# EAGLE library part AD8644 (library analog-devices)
Single and Quad 18 V Operational Amplifiers Source: http://www.analog.com/static/imported-files/data_sheets/AD8614_8644.pdf
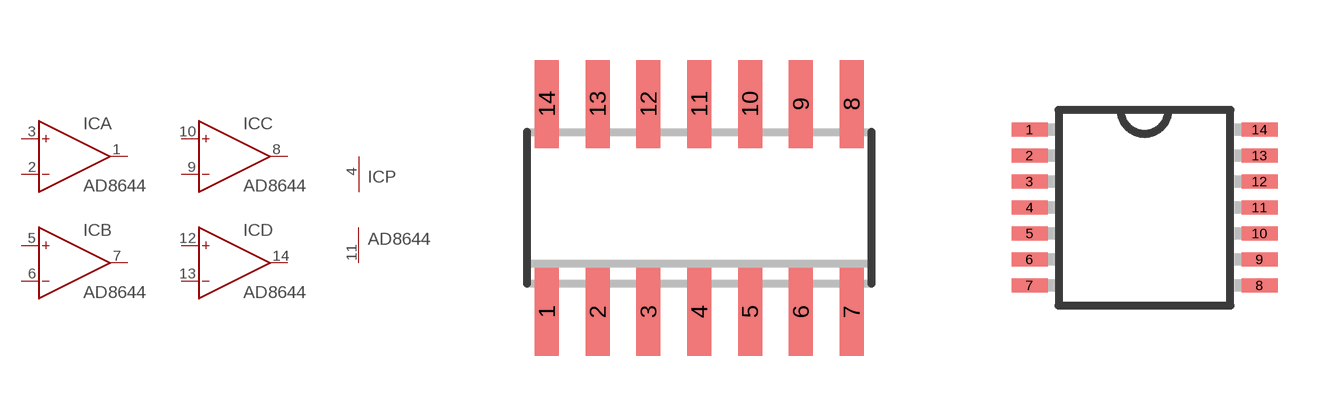
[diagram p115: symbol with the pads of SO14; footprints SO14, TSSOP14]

Designator prefix IC; gates A=OP B=OP C=OP D=OP P=PWR+-

## AD8644R (MF: ALTERA CORPORATION; MPN: AD8644ARZ; OC_FARNELL: 1438873; OC_NEWARK: 59K7037)  [SO14]
1  A:OUT  out
2  A:IN-  in
3  A:IN+  in
4  P:V+  pwr
5  B:IN+  in
6  B:IN-  in
7  B:OUT  out
8  C:OUT  out
9  C:IN-  in
10  C:IN+  in
11  P:V-  pwr
12  D:IN+  in
13  D:IN-  in
14  D:OUT  out

## AD8644RU (MF: ALTERA CORPORATION; MPN: AD8644ARUZ; OC_FARNELL: 1438873; OC_NEWARK: 59K7036)  [TSSOP14]
Pads as for SO14

## Footprint SO14 (pad centres in mm)
14-Lead Narrow-Body SOIC (SO-14) Source: http://www.analog.com/static/imported-files/data_sheets/SSM2166.pdf
smd 0.6 x 2.2: 1 -3.81,-2.6; 2 -2.54,-2.6; 3 -1.27,-2.6; 4 0,-2.6; 5 1.27,-2.6; 6 2.54,-2.6; 7 3.81,-2.6; 8 3.81,2.6; 9 2.54,2.6; 10 1.27,2.6; 11 0,2.6; 12 -1.27,2.6; 13 -2.54,2.6; 14 -3.81,2.6

## Footprint TSSOP14 (pad centres in mm)
14-Lead Thin Shrink Small Outline Package [TSSOP] Source: Analog Devices .. 780914713ADD8704_0.pdf
smd 0.9 x 0.35: 1 -2.875,1.95; 2 -2.875,1.3; 3 -2.875,0.65; 4 -2.875,0; 5 -2.875,-0.65; 6 -2.875,-1.3; 7 -2.875,-1.95; 8 2.875,-1.95; 9 2.875,-1.3; 10 2.875,-0.65; 11 2.875,0; 12 2.875,0.65; 13 2.875,1.3; 14 2.875,1.95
